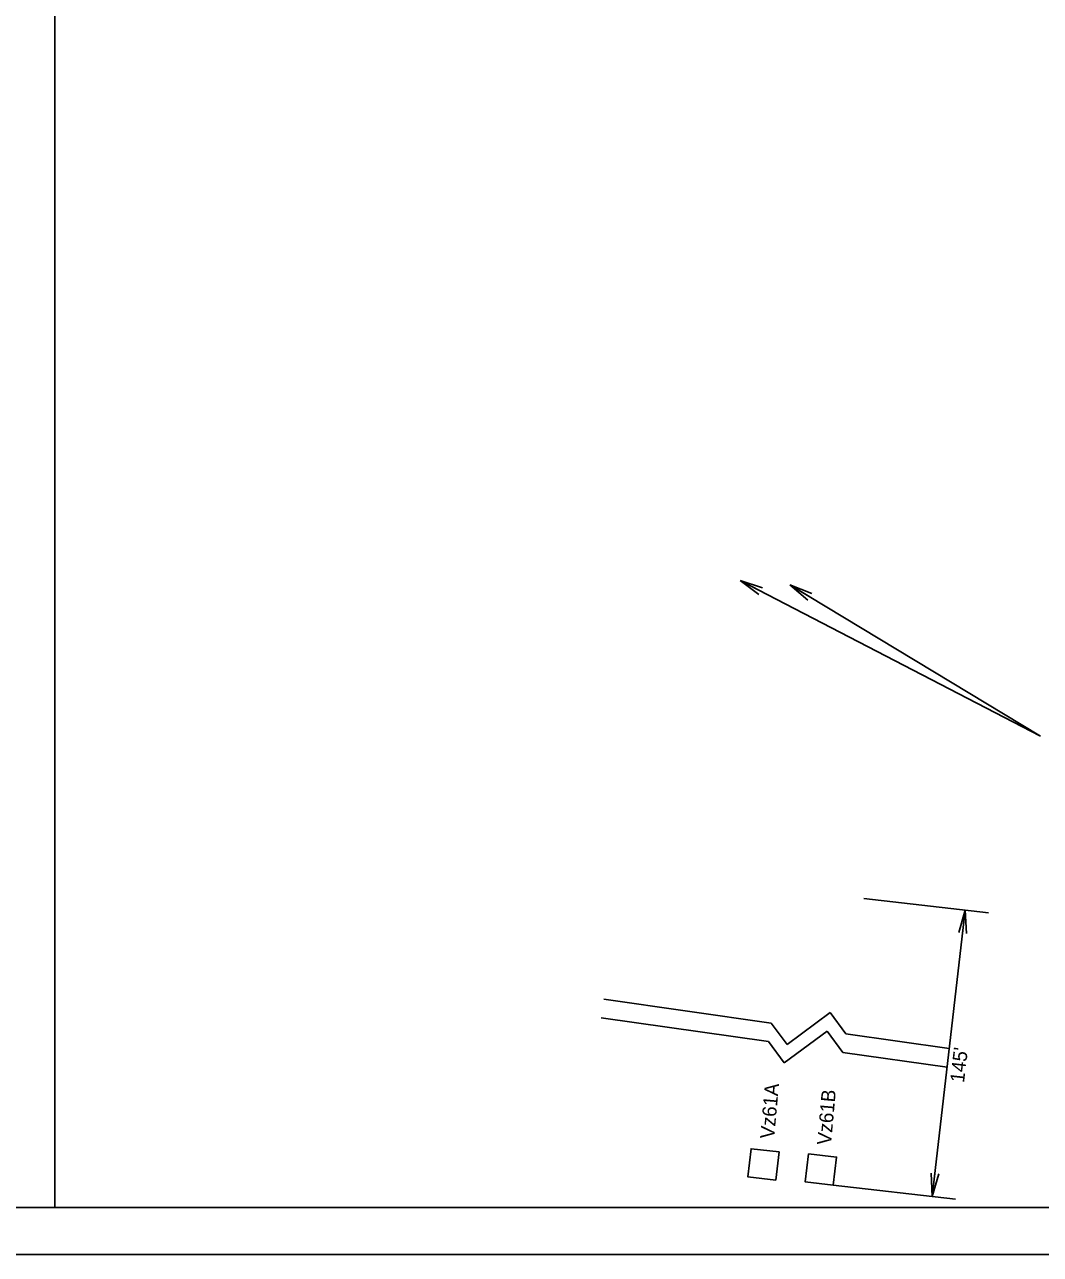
# Model space of a CAD drawing. Extents: x 635746 to 638310, y 744089 to 745312.
# Drawn here: x 636165.6 to 636381.6, y 744778.7 to 745040.1 of the extents above; entities that cross this region are included whole.
import ezdxf

# ---------------------------------------------------------------- set-up
doc = ezdxf.new("R2010")
doc.units = 0
for name, color, linetype in [('R_Border', 7, 'Continuous'), ('R_Dimension', 7, 'Continuous'), ('R_Grid', 7, 'Continuous'), ('R_No Plot', 7, 'Continuous'), ('T_Detection Zones', 7, 'Continuous'), ('T_Notes', 7, 'Continuous')]:
    doc.layers.add(name, color=color, linetype=linetype)

msp = doc.modelspace()

# ---------------------------------------------------------------- linework, layer by layer
at = {"layer": 'R_Border'}
msp.add_line((636567.25, 744788.65), (635776.8, 744788.65), dxfattribs=at)
at = {"layer": 'R_Dimension'}
for p, q in [((636370.59, 744851.34), (636344.04, 744854.39)), ((636365.62, 744851.91), (636358.61, 744791)), ((636364.24, 744847.1), (636365.62, 744851.91)), ((636365.62, 744851.91), (636365.06, 744847.01)), ((636365.62, 744851.91), (636365.88, 744846.91)), ((636288.79, 744832.98), (636324.4, 744827.87)), ((636288.18, 744829.02), (636323.79, 744823.92)), ((636327.75, 744823.35), (636336.88, 744830.13)), ((636340.24, 744825.6), (636336.88, 744830.13)), ((636324.4, 744827.87), (636327.75, 744823.35)), ((636327.15, 744819.4), (636336.28, 744826.17)), ((636336.28, 744826.17), (636339.63, 744821.65)), ((636323.79, 744823.92), (636327.15, 744819.4)), ((636340.24, 744825.6), (636362.23, 744822.45)), ((636339.63, 744821.65), (636361.77, 744818.48)), ((636358.61, 744791), (636358.36, 744795.99)), ((636358.61, 744791), (636359.17, 744795.9)), ((636359.99, 744795.8), (636358.61, 744791)), ((636363.57, 744790.43), (636337.58, 744793.42))]:
    msp.add_line(p, q, dxfattribs=at)
at = {"layer": 'R_Grid'}
msp.add_line((636172.02, 744788.65), (636172.02, 745302.3), dxfattribs=at)
at = {"layer": 'R_No Plot'}
msp.add_line((635745.8, 744778.7), (636579.13, 744778.7), dxfattribs=at)
msp.add_lwpolyline([(635745.78, 745312.04), (636579.13, 745312.04), (636579.13, 744778.69), (635745.78, 744778.69)], close=True, dxfattribs=at)
at = {"layer": 'T_Detection Zones'}
for points in [[(636325.35, 744794.51), (636319.39, 744795.2), (636320.08, 744801.16), (636326.04, 744800.47)], [(636337.58, 744793.42), (636331.62, 744794.11), (636332.31, 744800.07), (636338.27, 744799.38)]]:
    msp.add_lwpolyline(points, close=True, dxfattribs=at)
at = {"layer": 'T_Notes'}
for p, q in [((636317.77, 744921.97), (636381.62, 744888.85)), ((636317.77, 744921.97), (636322.53, 744920.43)), ((636321.77, 744918.97), (636317.77, 744921.97)), ((636317.77, 744921.97), (636322.15, 744919.7)), ((636381.62, 744888.85), (636328.36, 744921.03)), ((636328.36, 744921.03), (636333.01, 744919.18)), ((636332.16, 744917.77), (636328.36, 744921.03)), ((636328.36, 744921.03), (636332.58, 744918.48))]:
    msp.add_line(p, q, dxfattribs=at)

# ---------------------------------------------------------------- texts
at = {"layer": 'R_Dimension'}
msp.add_text("145'", height=3, rotation=83.4101, dxfattribs=at).set_placement((636365.38, 744815.11))
at = {"layer": 'T_Detection Zones'}
for s, p in [('Vz61A', (636324.99, 744803.17)), ('Vz61B', (636337.08, 744801.84))]:
    msp.add_text(s, height=3, rotation=84.8478, dxfattribs=at).set_placement(p)

doc.saveas('drawing.dxf')
